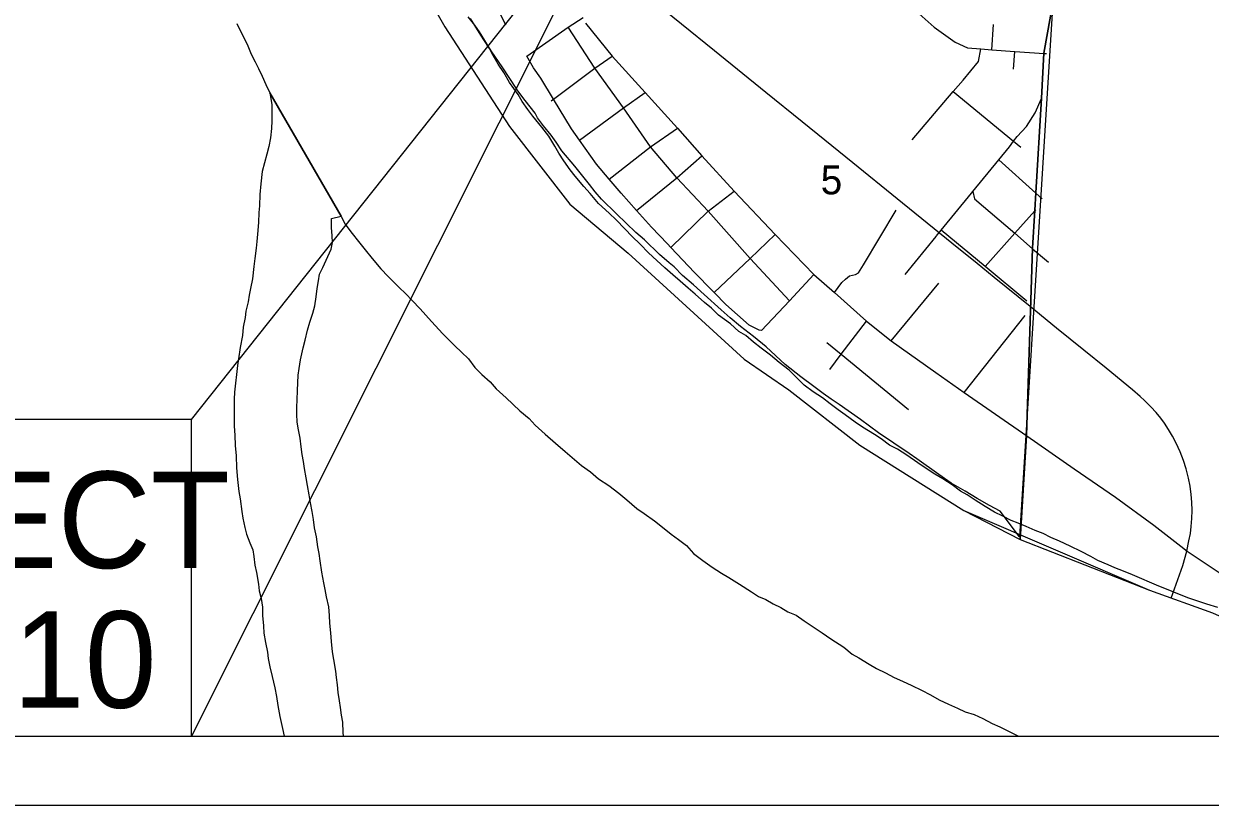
# Model space of a CAD drawing. Extents: x 0 to 45.4, y -2.2 to 22.
# Drawn here: x 3.344 to 5.063, y 14 to 15.133 of the extents above; entities that cross this region are included whole.
import ezdxf

# ---------------------------------------------------------------- set-up
doc = ezdxf.new("R2010")
doc.units = 0
for name, color, linetype in [('GM_X_City_Street', 7, 'Continuous'), ('GM_X_Corporation', 7, 'Continuous'), ('GM_X_County_Road', 7, 'Continuous'), ('GM_X_Major_River', 7, 'Continuous'), ('GM_X_Rail_Line', 7, 'Continuous'), ('GM_X_Section_Text', 7, 'Continuous'), ('SH_Data', 7, 'Continuous'), ('SH_Text', 7, 'Continuous')]:
    doc.layers.add(name, color=color, linetype=linetype)

msp = doc.modelspace()

# ---------------------------------------------------------------- linework, layer by layer
at = {"layer": 'GM_X_City_Street'}
for p, q in [((4.747, 15.0953), (4.7493, 15.132)), ((4.7781, 15.0671), (4.7803, 15.0929)), ((4.6009, 14.6734), (4.67, 14.7569)), ((4.7066, 14.5986), (4.7952, 14.7101))]:
    msp.add_line(p, q, dxfattribs=at)
for points in [[(4.0425, 15.1307), (4.0224, 15.1713), (4.0155, 15.1853), (3.9884, 15.2383), (3.9848, 15.2453), (3.9573, 15.289), (3.9383, 15.3215)], [(4.6291, 15.1956), (4.6288, 15.1688), (4.6369, 15.1512), (4.6632, 15.1281), (4.6936, 15.1061), (4.7114, 15.0979), (4.7308, 15.0965), (4.747, 15.0953), (4.7803, 15.0929), (4.8225, 15.0899), (4.8258, 15.0897)], [(4.0728, 15.086), (4.1329, 15.1279), (4.1545, 15.1419)], [(4.4536, 14.7315), (4.3965, 14.7927), (4.3357, 14.8614), (4.2902, 14.9095), (4.2521, 14.9547), (4.2132, 15.0109), (4.1716, 15.0686), (4.1329, 15.1279)], [(4.342, 14.7457), (4.3157, 14.7726), (4.2814, 14.8085), (4.2765, 14.8137), (4.2535, 14.8379), (4.2318, 14.8622), (4.2094, 14.8874), (4.1924, 14.9076), (4.1739, 14.9296), (4.1493, 14.9643), (4.1377, 14.9806), (4.1116, 15.0238), (4.093, 15.0543), (4.0826, 15.0692), (4.0728, 15.086)], [(4.108, 15.0211), (4.1116, 15.0238), (4.1716, 15.0686), (4.1963, 15.0858)], [(4.6312, 14.9647), (4.6909, 15.0346), (4.7051, 15.0512), (4.7274, 15.0783), (4.7308, 15.0965)], [(4.1493, 14.9643), (4.2132, 15.0109), (4.2445, 15.0335)], [(4.6909, 15.0346), (4.7783, 14.9628), (4.7888, 14.9541)], [(4.6667, 14.8253), (4.6735, 14.8337), (4.7172, 14.8872), (4.7191, 14.8896), (4.7567, 14.9358), (4.7722, 14.9547), (4.7783, 14.9628), (4.7833, 14.9694), (4.7968, 14.984), (4.8095, 15.0036), (4.8189, 15.0248)], [(4.1924, 14.9076), (4.2521, 14.9547), (4.2911, 14.9815)], [(4.2318, 14.8622), (4.2902, 14.9095), (4.3263, 14.9414)], [(4.7567, 14.9358), (4.8107, 14.8874), (4.8198, 14.8793)], [(4.2814, 14.8085), (4.3357, 14.8614), (4.3734, 14.8904)], [(4.7191, 14.8896), (4.7216, 14.8793), (4.78, 14.8292), (4.8059, 14.8069), (4.8289, 14.7872)], [(4.5186, 14.7436), (4.5293, 14.7578), (4.5346, 14.7629), (4.5404, 14.7676), (4.549, 14.7694), (4.5533, 14.7721), (4.5608, 14.7834), (4.6083, 14.8628)], [(4.737, 14.7809), (4.78, 14.8292), (4.8092, 14.862), (4.8105, 14.8634)], [(4.3442, 14.7435), (4.3965, 14.7927), (4.4329, 14.8275)], [(4.6212, 14.7696), (4.666, 14.8245), (4.6667, 14.8253)], [(4.7975, 14.7307), (4.737, 14.7809), (4.6735, 14.8337)], [(4.4132, 14.6882), (4.4536, 14.7315), (4.4889, 14.7694)], [(4.4132, 14.6882), (4.4094, 14.6886), (4.3951, 14.696), (4.3613, 14.7261), (4.3447, 14.743), (4.3442, 14.7435), (4.342, 14.7457)], [(4.5118, 14.6319), (4.5286, 14.6539), (4.5652, 14.7017)], [(4.5078, 14.6711), (4.5286, 14.6539), (4.626, 14.5736)]]:
    msp.add_lwpolyline(points, dxfattribs=at)
at = {"layer": 'GM_X_Corporation'}
for points in [[(3.8978, 15.2272), (3.9542, 15.1285), (4.0477, 14.9842), (4.1352, 14.8715), (4.2196, 14.8002), (4.388, 14.6465), (4.4527, 14.6021), (4.5557, 14.522), (4.7063, 14.4272), (4.7879, 14.3851), (4.9751, 14.3119), (5.0667, 14.2789), (5.1988, 14.2201), (5.2415, 14.2027), (5.3809, 14.1693), (5.499, 14.1314), (5.6021, 14.1), (7.0413, 14.1)], [(3.8978, 15.2272), (3.9542, 15.1285), (4.0477, 14.9842), (4.1352, 14.8715), (4.2196, 14.8002), (4.388, 14.6465), (4.4527, 14.6021), (4.5557, 14.522), (4.7063, 14.4272), (4.7879, 14.3851), (4.7972, 14.536), (4.8057, 14.8075), (4.809, 14.8625), (4.8105, 14.8879), (4.8187, 15.0253), (4.8223, 15.0904), (4.8407, 15.1929)], [(3.8978, 15.2272), (3.9542, 15.1285), (4.0477, 14.9842), (4.1352, 14.8715), (4.2196, 14.8002), (4.388, 14.6465), (4.4527, 14.6021), (4.5557, 14.522), (4.7063, 14.4272), (4.9751, 14.3119), (5.0667, 14.2789), (5.1988, 14.2201), (5.2415, 14.2027), (5.3809, 14.1693), (5.6023, 14.1), (5.6624, 14.1), (5.7213, 14.2916), (5.8523, 14.276), (5.9392, 14.8581), (5.9392, 15.1293), (5.6491, 15.1452)], [(4.837, 15.1953), (4.7868, 14.3891), (4.7588, 14.4266), (4.7436, 14.4345), (4.7254, 14.4448), (4.708, 14.4554), (4.6876, 14.4672), (4.6701, 14.4793), (4.638, 14.5021), (4.627, 14.51), (4.5827, 14.54), (4.5562, 14.5593), (4.5255, 14.5809), (4.5141, 14.5885), (4.5024, 14.5969), (4.4887, 14.6071), (4.4698, 14.6211), (4.4471, 14.639), (4.4195, 14.6644), (4.4013, 14.6795), (4.3827, 14.694), (4.3676, 14.7068), (4.3547, 14.7182), (4.3301, 14.7406), (4.3142, 14.7546), (4.2987, 14.7679), (4.2862, 14.7804), (4.2793, 14.7865), (4.265, 14.7986), (4.2434, 14.8195), (4.2309, 14.8305), (4.2029, 14.8574), (4.1813, 14.8786), (4.1718, 14.8892), (4.1635, 14.8998), (4.1423, 14.9264), (4.1237, 14.9487), (4.1154, 14.9612), (4.1082, 14.9715), (4.0972, 14.9851), (4.0885, 14.9965), (4.0848, 15.0033), (4.0704, 15.0219), (4.0598, 15.0355), (4.0575, 15.0397), (4.0382, 15.0689), (4.0212, 15.0939), (4.0045, 15.1212), (3.9973, 15.1311), (3.9879, 15.1428)], [(4.8407, 15.1929), (4.8223, 15.0904), (4.8187, 15.0253), (4.8105, 14.8879), (4.809, 14.8625), (4.8057, 14.8075), (4.7972, 14.536), (4.7879, 14.3851), (4.9751, 14.3119), (5.0667, 14.2789), (5.1988, 14.2201), (5.2415, 14.2027), (5.3809, 14.1693), (5.499, 14.1314), (5.6021, 14.1), (7.0413, 14.1)]]:
    msp.add_lwpolyline(points, dxfattribs=at)
at = {"layer": 'GM_X_County_Road'}
for points in [[(4.1578, 15.134), (4.1963, 15.0858), (4.2445, 15.0335), (4.2911, 14.9815), (4.3263, 14.9414), (4.3734, 14.8904), (4.4329, 14.8275), (4.4889, 14.7694), (4.5186, 14.7436), (4.5652, 14.7017), (4.6009, 14.6734), (4.6656, 14.6273), (4.7066, 14.5986), (4.7974, 14.5355), (4.8663, 14.4876), (4.9261, 14.4468), (4.9817, 14.4061), (5.0206, 14.3757)], [(5.0206, 14.3757), (5.0301, 14.3683), (5.1039, 14.3189), (5.1401, 14.2949), (5.1705, 14.2785), (5.2488, 14.2548), (5.2884, 14.2414), (5.3455, 14.2246), (5.38, 14.2156), (5.4034, 14.211)]]:
    msp.add_lwpolyline(points, dxfattribs=at)
at = {"layer": 'GM_X_Major_River'}
for p, q in [((3.7005, 15.0329), (3.8037, 14.8538)), ((3.8037, 14.8538), (3.7005, 15.0329))]:
    msp.add_line(p, q, dxfattribs=at)
for points in [[(3.6525, 15.1331), (3.6619, 15.1145), (3.6676, 15.1035), (3.6733, 15.089), (3.6793, 15.0776), (3.6838, 15.0682), (3.6891, 15.0568), (3.6944, 15.045), (3.7005, 15.0329)], [(4.3508, 14.7107), (4.3406, 14.7206), (4.3304, 14.7289), (4.3168, 14.7411), (4.3066, 14.7498), (4.2952, 14.7597), (4.2843, 14.7692), (4.2729, 14.779), (4.2612, 14.7896), (4.2491, 14.801), (4.237, 14.8132), (4.2253, 14.8245), (4.2151, 14.8356), (4.2022, 14.8485), (4.1924, 14.8583), (4.1769, 14.8724), (4.1648, 14.8868), (4.1553, 14.897), (4.1429, 14.9118), (4.1357, 14.9213), (4.1266, 14.9342), (4.1191, 14.9456), (4.1134, 14.9555), (4.1047, 14.9699), (4.0945, 14.9832), (4.0816, 14.9991), (4.0744, 15.0086), (4.0661, 15.0203), (4.0605, 15.0302), (4.0476, 15.0477), (4.0393, 15.0621), (4.0314, 15.0746), (4.0242, 15.0871), (4.0189, 15.097), (4.0106, 15.1095), (4.0038, 15.1205), (3.9973, 15.1304), (3.9913, 15.1406)], [(3.7005, 15.0329), (3.7031, 15.0158), (3.7035, 15.0029), (3.7035, 14.9923), (3.7027, 14.9809), (3.7012, 14.9676), (3.6989, 14.9551), (3.6959, 14.9437), (3.6891, 14.9187), (3.6872, 14.9008), (3.6861, 14.8856), (3.6853, 14.869), (3.6845, 14.8595), (3.6838, 14.845), (3.6823, 14.828), (3.6815, 14.8174), (3.6807, 14.8075), (3.6788, 14.7927), (3.677, 14.7809), (3.6751, 14.7631), (3.6724, 14.7491), (3.6705, 14.7396), (3.669, 14.7297), (3.6656, 14.7164), (3.6645, 14.707), (3.6618, 14.6933), (3.6607, 14.6808), (3.6576, 14.6637), (3.655, 14.6474), (3.6535, 14.6375), (3.652, 14.6243), (3.6508, 14.6121), (3.6493, 14.5988), (3.6489, 14.5886), (3.6485, 14.5765), (3.6485, 14.5636), (3.6489, 14.5495), (3.6497, 14.5366), (3.6504, 14.5218), (3.6515, 14.5067), (3.6523, 14.4892), (3.6534, 14.4721), (3.6557, 14.4547), (3.6576, 14.4441), (3.6598, 14.4259), (3.6613, 14.416), (3.664, 14.4027), (3.6666, 14.3929), (3.6712, 14.3807), (3.6757, 14.3701), (3.6772, 14.3606), (3.6787, 14.3481), (3.681, 14.3375), (3.684, 14.3204), (3.6851, 14.3109), (3.6878, 14.2996), (3.6897, 14.287), (3.69, 14.2749), (3.6912, 14.2601), (3.6919, 14.2495), (3.6942, 14.2362), (3.6968, 14.2222), (3.698, 14.2127), (3.7006, 14.2006), (3.7036, 14.1865), (3.7078, 14.1702), (3.71, 14.1577), (3.7119, 14.1448), (3.715, 14.1289), (3.7187, 14.1114), (3.7213, 14.1)], [(3.807, 14.1), (3.8068, 14.1057), (3.8061, 14.1205), (3.8042, 14.1304), (3.8027, 14.1418), (3.8012, 14.1513), (3.7993, 14.1634), (3.7985, 14.1744), (3.797, 14.185), (3.7959, 14.1945), (3.7933, 14.2112), (3.7914, 14.2226), (3.7899, 14.2373), (3.7887, 14.2499), (3.7876, 14.2639), (3.7868, 14.2753), (3.7857, 14.2878), (3.7827, 14.3022), (3.7804, 14.3128), (3.7789, 14.3227), (3.7759, 14.3379), (3.7733, 14.3545), (3.7717, 14.3648), (3.7702, 14.3747), (3.768, 14.3891), (3.7653, 14.4023), (3.7638, 14.4141), (3.7619, 14.4259), (3.7593, 14.4384), (3.7574, 14.4501), (3.7548, 14.4638), (3.7529, 14.4748), (3.7506, 14.4881), (3.7491, 14.4983), (3.7472, 14.5085), (3.7457, 14.5195), (3.7442, 14.5324), (3.7419, 14.5442), (3.74, 14.5556), (3.7393, 14.567), (3.7393, 14.5772), (3.74, 14.5878), (3.7404, 14.6015), (3.7408, 14.6125), (3.7416, 14.6235), (3.7427, 14.633), (3.745, 14.6459), (3.7488, 14.6633), (3.7514, 14.6743), (3.7552, 14.6887), (3.7586, 14.7005), (3.7628, 14.7134), (3.7658, 14.724), (3.7677, 14.7373), (3.7692, 14.7491), (3.7707, 14.7601), (3.7726, 14.7699), (3.7772, 14.7794), (3.7893, 14.806), (3.7912, 14.8158), (3.7908, 14.8257), (3.7897, 14.8375), (3.79, 14.8507), (3.8037, 14.8538)], [(3.8037, 14.8538), (3.8093, 14.8428), (3.8195, 14.8287), (3.829, 14.8173), (3.8388, 14.8052), (3.8486, 14.7927), (3.8611, 14.7779), (3.8717, 14.7665), (3.8876, 14.7509), (3.8974, 14.7415), (3.9068, 14.732), (3.9182, 14.7195), (3.9348, 14.7012), (3.9511, 14.6834), (3.9685, 14.666), (3.9783, 14.6569), (3.9881, 14.647), (3.9976, 14.6345), (4.0078, 14.6246), (4.0195, 14.614), (4.0286, 14.6037), (4.0429, 14.5908), (4.0626, 14.5719), (4.0762, 14.5605), (4.0849, 14.551), (4.0993, 14.5381), (4.1144, 14.5248), (4.1284, 14.5127), (4.142, 14.5013), (4.1522, 14.4926), (4.165, 14.4835), (4.1768, 14.4732), (4.1919, 14.4638), (4.2063, 14.4524), (4.2176, 14.4429), (4.2323, 14.4304), (4.2429, 14.4228), (4.2577, 14.4125), (4.272, 14.4012), (4.2819, 14.3928), (4.2925, 14.3852), (4.3042, 14.3765), (4.3144, 14.3651), (4.328, 14.3549), (4.3416, 14.345), (4.3552, 14.3363), (4.3658, 14.3302), (4.3813, 14.3204), (4.3987, 14.3094), (4.4085, 14.3029), (4.4191, 14.2984), (4.4297, 14.2919), (4.441, 14.2866), (4.4513, 14.2805), (4.463, 14.2756), (4.4747, 14.2673), (4.4879, 14.2589), (4.5008, 14.2502), (4.5136, 14.2411), (4.5325, 14.229), (4.5443, 14.2191), (4.5541, 14.2138), (4.5688, 14.2047), (4.5798, 14.1982), (4.5927, 14.1918), (4.6051, 14.1853), (4.6172, 14.18), (4.6308, 14.1736), (4.6448, 14.1671), (4.6577, 14.1603), (4.6705, 14.1527), (4.6842, 14.1466), (4.697, 14.141), (4.708, 14.1356), (4.7212, 14.1315), (4.7337, 14.1258), (4.7473, 14.1186), (4.7583, 14.1136), (4.7707, 14.1076), (4.7855, 14.1)], [(5.0745, 14.2866), (5.0586, 14.2916), (5.0325, 14.3003), (5.0189, 14.3056), (5.0023, 14.3121), (4.989, 14.3177), (4.9754, 14.3234), (4.9641, 14.3284), (4.9505, 14.3341), (4.9376, 14.3394), (4.9251, 14.3443), (4.9153, 14.3485), (4.9002, 14.3549), (4.8903, 14.3606), (4.8763, 14.3678), (4.8601, 14.3758), (4.845, 14.383), (4.8325, 14.3883), (4.8211, 14.394), (4.8094, 14.3985), (4.7966, 14.4042), (4.7848, 14.4091), (4.7746, 14.4126), (4.7625, 14.419), (4.7508, 14.4247), (4.7372, 14.433), (4.7228, 14.4421), (4.7111, 14.4501), (4.7013, 14.4554), (4.6895, 14.4645), (4.6759, 14.4732), (4.6642, 14.4801), (4.6514, 14.4884), (4.6396, 14.4964), (4.6238, 14.5074), (4.6102, 14.5161), (4.5984, 14.5222), (4.5863, 14.5313), (4.5765, 14.5374), (4.5595, 14.548), (4.5489, 14.5556), (4.5342, 14.5658), (4.5243, 14.5734), (4.5126, 14.5821), (4.5013, 14.5905), (4.488, 14.5996), (4.4748, 14.6091), (4.4631, 14.6204), (4.4529, 14.6307), (4.4385, 14.6421), (4.426, 14.6523), (4.4124, 14.6625), (4.4015, 14.6716), (4.3901, 14.6808), (4.3803, 14.6868), (4.3678, 14.6978), (4.3508, 14.7107)]]:
    msp.add_lwpolyline(points, dxfattribs=at)
at = {"layer": 'GM_X_Rail_Line'}
msp.add_lwpolyline([(5.0066, 14.3001), (5.0236, 14.3474), (5.0296, 14.3683), (5.0325, 14.3832), (5.0345, 14.3939), (5.0358, 14.4043), (5.0368, 14.4156), (5.0369, 14.4273), (5.0366, 14.4395), (5.0357, 14.4506), (5.034, 14.4624), (5.0316, 14.4741), (5.0282, 14.4879), (5.0244, 14.4997), (5.0196, 14.5123), (5.0138, 14.5248), (5.0088, 14.5349), (5.0028, 14.5449), (4.9969, 14.554), (4.9917, 14.5612), (4.9849, 14.5696), (4.9773, 14.5777), (4.9682, 14.5869), (4.9619, 14.5926), (4.9508, 14.6025), (4.9126, 14.6336), (4.88, 14.6597), (4.8406, 14.6917), (4.8023, 14.7231), (4.75, 14.7651), (4.7254, 14.7852), (4.6887, 14.815), (4.6094, 14.8794), (4.5451, 14.9313), (4.5047, 14.9642), (4.472, 14.9906), (4.4194, 15.0334), (4.3448, 15.0937), (4.2492, 15.1716)], dxfattribs=at)
at = {"layer": 'SH_Data'}
for p, q in [((2.1, 14.1), (8.9, 14.1)), ((2, 14), (9, 14))]:
    msp.add_line(p, q, dxfattribs=at)
at = {"layer": 'SH_Text'}
for points in [[(3.5871, 14.5594), (4.2105, 15.3448), (3.5871, 14.1)], [(3.5871, 14.5594), (2.1, 14.5594), (2.1, 14.1), (3.5871, 14.1)]]:
    msp.add_lwpolyline(points, close=True, dxfattribs=at)

# ---------------------------------------------------------------- texts
at = {"layer": 'GM_X_Section_Text'}
msp.add_text('5', height=0.0419, rotation=0, dxfattribs=at).set_placement((4.4988, 14.8857))
at = {"layer": 'SH_Text'}
for s, p in [('BEGIN PROJECT', (2.1341, 14.3438)), ('STA. 5+49.10', (2.3862, 14.1413))]:
    msp.add_text(s, height=0.14, dxfattribs=at).set_placement(p)

doc.saveas('drawing.dxf')
